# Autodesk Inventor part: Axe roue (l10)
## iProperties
Author: Flavien MARTY
Shininess: 60.0
PropertySet Name: _Private Model Information
Created: 2001-10
Part Number: Axe roue (l10)
Material: Par défaut
Document SubType Name: Modélisation
Designer: Flavien MARTY
Control State: 0
Master: False
Checked Out: False
PropertySet Name: Design Tracking Control
Density: 0.0
Volumn: 0.0
Area: 0.0
PropertySet Name: Model Information
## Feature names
1. Base1
